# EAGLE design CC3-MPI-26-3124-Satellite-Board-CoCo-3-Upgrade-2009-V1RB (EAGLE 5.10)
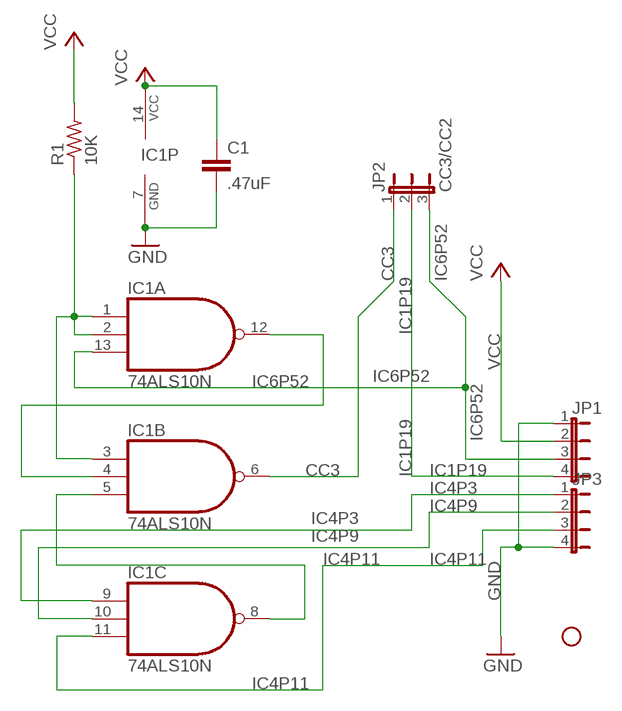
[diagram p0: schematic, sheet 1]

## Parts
C1  .47uF  C2.5/4  [C2.5-4]
IC1  74ALS10N  [DIL14-3]
JP1  JP4E  [JP4]
JP2  CC3/CC2  JP2E  [JP2]
JP3  JP4E  [JP4]
R1  10K  R-US_0207/7  [0207/7]
U$1  SPARKFUN_STAND-OFF  [SPARKFUN_STAND-OFF]

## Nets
CC3: IC1.6(B:O) JP2.1
GND [power]: C1.2 IC1.7(P:GND) JP1.1 JP3.4
IC1P19: JP1.4 JP2.2
IC4P3: IC1.9(C:I0) JP3.1
IC4P9: IC1.10(C:I1) JP3.2
IC4P11: IC1.11(C:I2) JP3.3
IC6P52: IC1.13(A:I2) JP1.3 JP2.3
N$6: IC1.1(A:I0) IC1.2(A:I1) IC1.3(B:I0) R1.1
N$8: IC1.4(B:I1) IC1.12(A:O)
N$9: IC1.5(B:I2) IC1.8(C:O)
VCC [power]: C1.1 IC1.14(P:VCC) JP1.2 R1.2

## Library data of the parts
C1 = capacitor-wima:C: CAPACITOR
IC1 = RetroZilla.org-74xx-us:74*10: Triple 3-input NAND gate
JP1 JP3 = jumper:JP4E: JUMPER
JP2 = jumper:JP2E: JUMPER
R1 = rcl-2:R-US_: RESISTOR, American symbol
U$1 = FDC:SPARKFUN_STAND-OFF: Stand Off

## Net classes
0 default: width 0.203 mm, clearance 0.152 mm
1 power: width 0.762 mm, clearance 0.203 mm

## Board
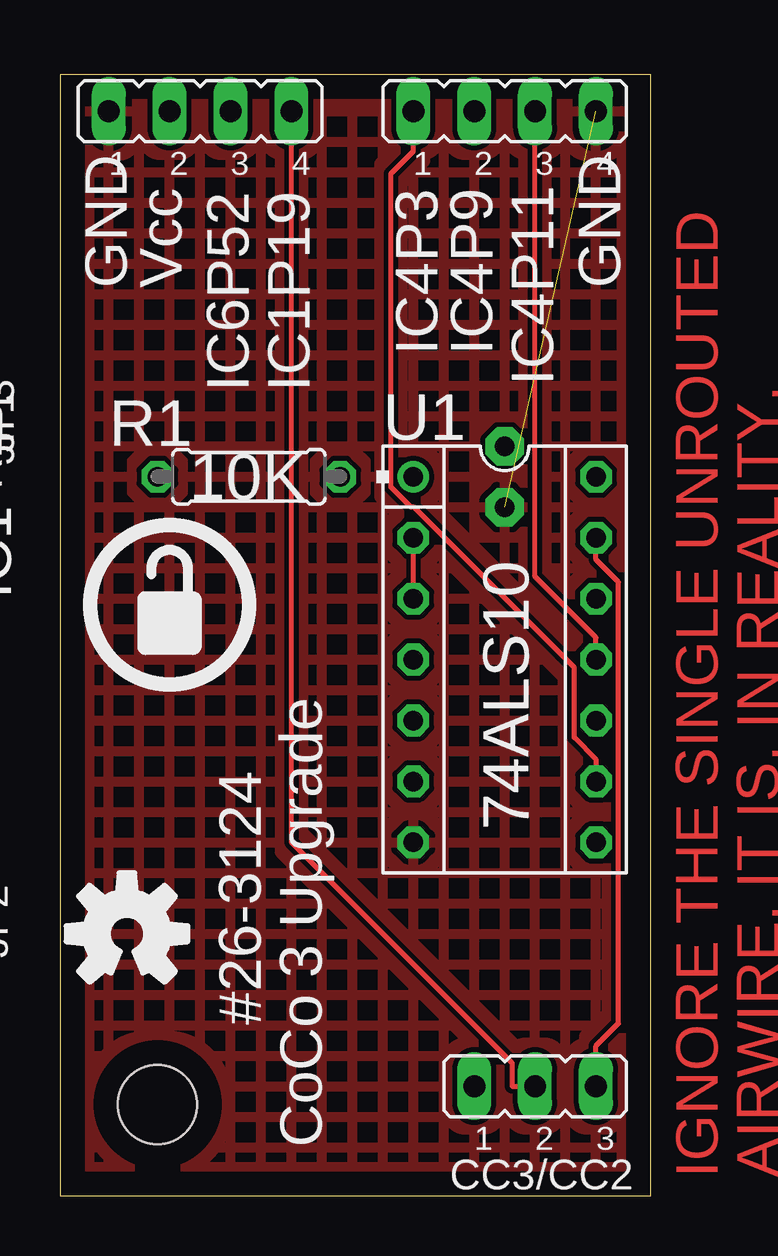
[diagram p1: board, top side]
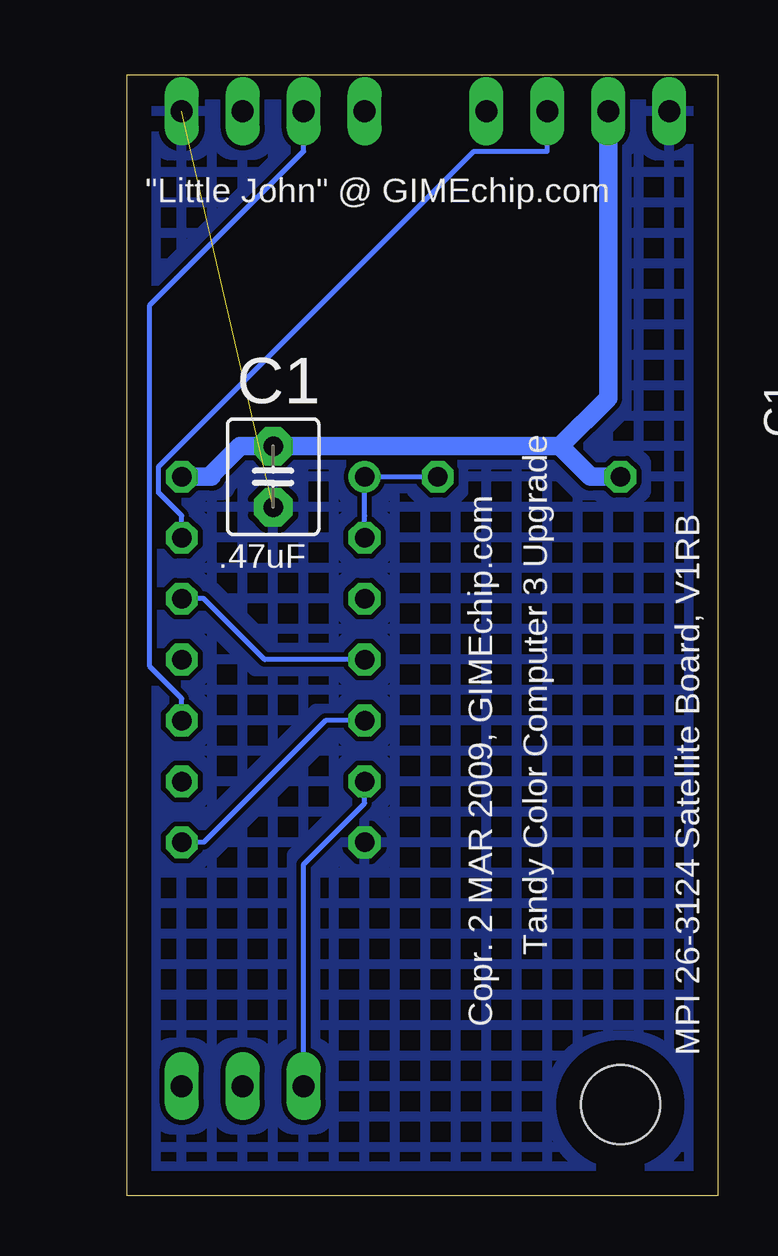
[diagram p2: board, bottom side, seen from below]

Size 24.64 x 46.74 mm. Coordinates in mm from the lower left corner, seen from the top.
Outline: 0,46.74 0,0 24.64,0 24.64,46.74 0,46.74
Copper layers (1*16): Top 0.035mm / dielectric 1.5mm / Bottom 0.035mm
Design rules "default": minimum track width 10mil, minimum drill 24mil, track to track 8mil, track to pad 8mil, pad to pad 8mil, via to via 8mil, smd to smd 8mil, copper to edge 40mil, drill to drill 8mil, minimum pad ring 10mil, minimum via ring 8mil, stop-mask expansion 4mil, vias tented up to drill 0mil, thermal gap 10mil

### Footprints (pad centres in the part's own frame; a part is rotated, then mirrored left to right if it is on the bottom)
C2.5-4 = drill 0.813 pad 1.6 octagon: 1 -1.27,0; 2 1.27,0
DIL14-3 = drill 0.813 round: 1 -7.62,-3.81 | drill 0.813 octagon: 2 -5.08,-3.81; 3 -2.54,-3.81; 4 0,-3.81; 5 2.54,-3.81; 6 5.08,-3.81; 7 7.62,-3.81; 8 7.62,3.81; 9 5.08,3.81; 10 2.54,3.81; 11 0,3.81; 12 -2.54,3.81; 13 -5.08,3.81; 14 -7.62,3.81
JP4 = drill 0.914 long: 1 -3.81,0; 2 -1.27,0; 3 1.27,0; 4 3.81,0
JP2 = drill 0.914 long: 1 -2.54,0; 2 0,0; 3 2.54,0
0207/7 = drill 0.813 octagon: 1 -3.81,0; 2 3.81,0
SPARKFUN_STAND-OFF = hole 3.302: 0,0

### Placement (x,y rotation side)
C1  18.54,29.97 270 bottom
IC1  18.54,22.35 270 top
JP1  5.84,45.21 0 top
JP2  19.81,4.57 0 top
JP3  18.54,45.21 0 top
R1  7.87,29.97 180 top
U$1  4.06,3.81 0 top
U$2  [OSHWLOGO_0.3]  4.57,24.64 0 top
U$3  [OSHWLOGO_TOL_0.2]  2.79,10.92 0 top

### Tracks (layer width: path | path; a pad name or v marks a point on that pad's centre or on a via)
CC3
  Bottom 0.203: IC1.6 14.73,16.36 17.27,13.82 JP2.1
GND  (1 unrouted)
  pour Top (hatched): -0.51,47.75 24.89,47.75 24.89,-0.51 -0.51,-0.51
  pour Bottom (hatched): -0.51,47.75 24.89,47.75 24.89,-0.51 -0.51,-0.51
IC1P19
  Top 0.203: JP2.2 18.85,4.57 18.85,5.54 9.65,14.73 JP1.4
IC4P3
  Top 0.203: JP3.1 14.73,43.54 13.8,42.6 13.8,29.54 14.64,28.7 14.77,28.7 21.44,22.03 21.44,19.1 22.35,18.19 IC1.9
IC4P9
  Bottom 0.203: IC1.10 22.35,20.73 23.69,22.06 23.69,37.12 17.27,43.54 JP3.2
IC4P11
  Top 0.203: IC1.11 22.35,23.27 19.81,25.81 JP3.3
IC6P52
  Top 0.203: IC1.13 22.35,26.52 23.29,25.58 23.29,7.19 22.35,6.25 JP2.3
  Bottom 0.203: JP1.3 7.11,43.54 10.18,43.54 23.32,30.4 23.32,29.31 22.35,28.35 IC1.13
N$6
  Top 0.203: IC1.3 IC1.2
  Bottom 0.203: IC1.2 14.73,28.35 IC1.1 R1.1
N$8
  Bottom 0.203: IC1.12 21.44,24.89 18.9,22.35 IC1.4
N$9
  Bottom 0.203: IC1.8 21.44,14.73 16.36,19.81 IC1.5
VCC
  Bottom 0.762: 6.58,31.24 C1.1 19.93,31.24 21.11,30.06 21.11,29.97 IC1.14 | 6.58,31.24 5.31,29.97 R1.2 | 6.58,31.24 4.57,33.25 JP1.2

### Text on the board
Top: IGNORE THE SINGLE UNROUTED | AIRWIRE. IT IS, IN REALITY, | CONNECTED VIA GND PLANE.
tPlace: GND | Vcc | GND | IC4P3 | IC4P9 | IC6P52 | IC1P19 | IC4P11 | R1 | U1 | 10K | 74ALS10
bPlace: "Little John" @ GIMEchip.com | C1 | Tandy Color Computer 3 Upgrade | Copr. 2 MAR 2009, GIMEchip.com | .47uF | MPI 26-3124 Satellite Board, V1RB
_tsilk: #26-3124 | CoCo 3 Upgrade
